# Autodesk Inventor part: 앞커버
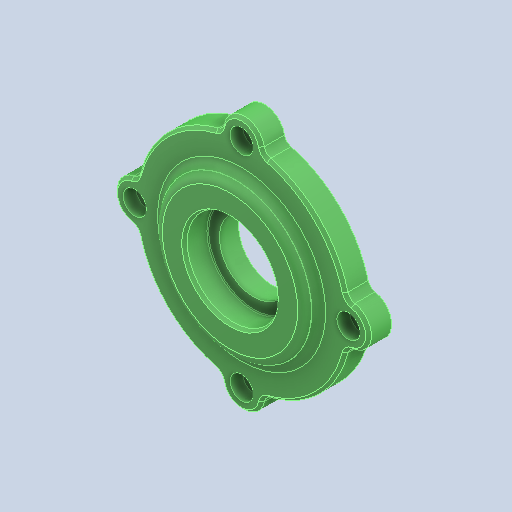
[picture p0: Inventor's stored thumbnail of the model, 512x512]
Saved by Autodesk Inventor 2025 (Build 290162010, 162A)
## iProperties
Created: 2024-08
Part Number: 앞커버
Material: 알루미늄 6061
Document SubType Name: Modeling
Designer: 학생
Density: 2.71 g/cm^3
Appearance: 기본값
Company: 한국ATC센터
Author: jhkim
Sending System: Autodesk Inventor 2025
Preprocessor: ST-DEVELOPER v20
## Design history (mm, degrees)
feature "솔리드1"
node "솔리드2"
